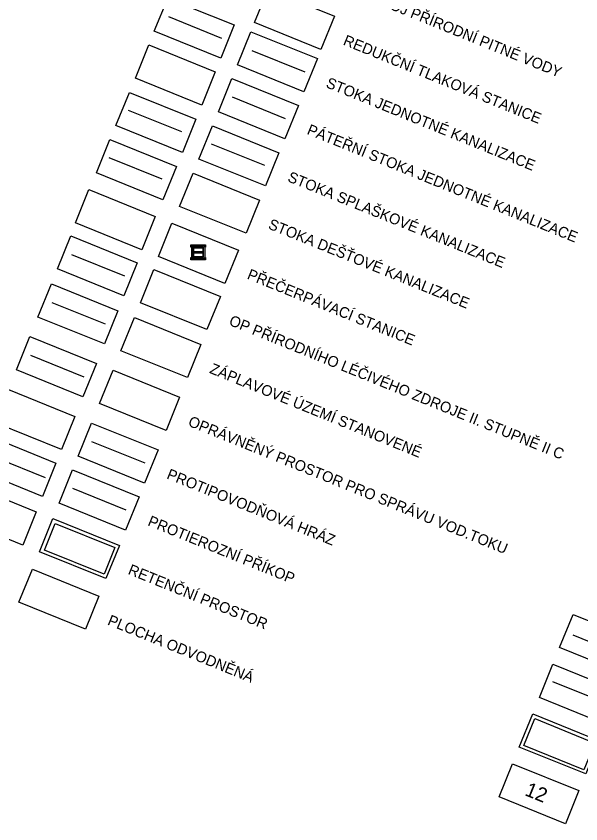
# Model space of a CAD drawing. Extents: x -522754 to -518969, y -1191121 to -1188171.
# Drawn here: x -520911 to -520123, y -1191020 to -1189893 of the extents above; entities that cross this region are included whole.
import ezdxf

# ---------------------------------------------------------------- set-up
doc = ezdxf.new("R2010")
doc.units = 0
for name, color, linetype in [('fpl_id', 7, 'Continuous'), ('hr_zast_uz_P_n', 7, 'Continuous'), ('HZU_P_s', 7, 'Continuous'), ('Implicitní', 7, 'Continuous'), ('kan_pater_j_n', 7, 'Continuous'), ('kan_stoka_j_n', 7, 'Continuous'), ('kan_stoka_j_s', 7, 'Continuous'), ('kan_stoka_s_n', 7, 'Continuous'), ('kan_stoka_s_s', 7, 'Continuous'), ('OPLZ_II_s', 7, 'Continuous'), ('pe_prikop_n', 7, 'Continuous'), ('pe_prikop_s', 7, 'Continuous'), ('pp_hraz_n', 7, 'Continuous'), ('ret_prostor_n', 7, 'Continuous'), ('sprava_toku_s', 7, 'Continuous'), ('zapl_uz_zdok_s', 7, 'Continuous'), ('zast_HD_s', 7, 'Continuous')]:
    doc.layers.add(name, color=color, linetype=linetype)

msp = doc.modelspace()

# ---------------------------------------------------------------- linework, layer by layer
at = {"layer": 'hr_zast_uz_P_n'}
msp.add_line((-520162.9, -1190821.2), (-520088.7, -1190851.2), dxfattribs=at)
at = {"layer": 'HZU_P_s'}
msp.add_line((-520134.5, -1190756.1), (-520060.4, -1190786.2), dxfattribs=at)
at = {"layer": 'Implicitní'}
for points in [[(-520559.8, -1189855.3), (-520467.1, -1189892.9), (-520485.9, -1189939.2), (-520578.5, -1189901.6)], [(-520699.6, -1189867.7), (-520606.9, -1189905.2), (-520625.7, -1189951.6), (-520718.4, -1189914)], [(-520583.7, -1189914.6), (-520491, -1189952.2), (-520509.8, -1189998.5), (-520602.5, -1189960.9)], [(-520726.1, -1189933), (-520633.4, -1189970.6), (-520652.2, -1190016.9), (-520744.8, -1189979.4)], [(-520610.2, -1189980), (-520517.5, -1190017.5), (-520536.3, -1190063.9), (-520629, -1190026.3)], [(-520753.2, -1189999.2), (-520660.5, -1190036.7), (-520679.3, -1190083), (-520772, -1190045.5)], [(-520637.3, -1190046), (-520544.6, -1190083.5), (-520563.4, -1190129.8), (-520656.1, -1190092.4)], [(-520780.3, -1190065.1), (-520687.6, -1190102.6), (-520706.4, -1190149), (-520799.1, -1190111.5)], [(-520664.4, -1190112), (-520571.7, -1190149.4), (-520590.5, -1190195.8), (-520683.2, -1190158.3)], [(-520809.6, -1190134.9), (-520717, -1190172.4), (-520735.7, -1190218.8), (-520828.4, -1190181.2)], [(-520693.8, -1190181.8), (-520601.1, -1190219.4), (-520619.9, -1190265.7), (-520712.6, -1190228.1)], [(-520834.9, -1190199.3), (-520742.2, -1190236.8), (-520761, -1190283.2), (-520853.7, -1190245.6)], [(-520719, -1190246.2), (-520626.3, -1190283.8), (-520645.1, -1190330.1), (-520737.8, -1190292.6)], [(-520862, -1190266.3), (-520769.4, -1190303.9), (-520788.1, -1190350.2), (-520880.8, -1190312.6)], [(-520746.2, -1190313.3), (-520653.5, -1190350.8), (-520672.3, -1190397.2), (-520765, -1190359.6)], [(-520891.9, -1190340), (-520799.2, -1190377.5), (-520818, -1190423.9), (-520910.7, -1190386.3)], [(-520776, -1190386.9), (-520683.4, -1190424.5), (-520702.1, -1190470.8), (-520794.8, -1190433.3)], [(-520921.7, -1190413.6), (-520829.1, -1190451.2), (-520847.8, -1190497.5), (-520940.5, -1190460)], [(-520805.9, -1190460.6), (-520713.2, -1190498.1), (-520732, -1190544.5), (-520824.7, -1190506.9)], [(-520948.2, -1190479), (-520855.6, -1190516.5), (-520874.3, -1190562.9), (-520967, -1190525.3)], [(-520832.4, -1190525.9), (-520739.7, -1190563.5), (-520758.5, -1190609.8), (-520851.2, -1190572.3)], [(-520975.7, -1190546.8), (-520883, -1190584.3), (-520901.8, -1190630.7), (-520994.5, -1190593.1)], [(-520859.9, -1190593.7), (-520767.2, -1190631.3), (-520786, -1190677.6), (-520878.6, -1190640.1)], [(-520888.5, -1190664.3), (-520795.8, -1190701.9), (-520814.6, -1190748.2), (-520907.2, -1190710.6)], [(-520134.3, -1190727.5), (-520041.6, -1190765), (-520060.4, -1190811.4), (-520153, -1190773.8)], [(-520162.4, -1190797), (-520069.7, -1190834.5), (-520088.5, -1190880.9), (-520181.2, -1190843.3)], [(-520190.5, -1190866.2), (-520097.8, -1190903.8), (-520116.6, -1190950.1), (-520209.3, -1190912.6)], [(-520187.6, -1190872.9), (-520103.8, -1190907), (-520119.1, -1190944.5), (-520202.9, -1190910.4)], [(-520218.7, -1190935.7), (-520126, -1190973.3), (-520144.8, -1191019.6), (-520237.4, -1190982.1)]]:
    msp.add_lwpolyline(points, close=True, dxfattribs=at)
at = {"layer": 'kan_pater_j_n'}
msp.add_line((-520610, -1190005.6), (-520535.9, -1190035.7), dxfattribs=at)
at = {"layer": 'kan_stoka_j_n'}
msp.add_line((-520582.5, -1189940.7), (-520508.3, -1189970.7), dxfattribs=at)
at = {"layer": 'kan_stoka_j_s'}
msp.add_line((-520698.8, -1189893.6), (-520624.6, -1189923.6), dxfattribs=at)
at = {"layer": 'kan_stoka_s_n'}
msp.add_line((-520639, -1190070.8), (-520564.8, -1190100.7), dxfattribs=at)
at = {"layer": 'kan_stoka_s_s'}
for p, q in [((-520754.9, -1190024), (-520680.7, -1190053.9)), ((-520781.9, -1190089.9), (-520707.8, -1190119.9))]:
    msp.add_line(p, q, dxfattribs=at)
at = {"layer": 'OPLZ_II_s'}
msp.add_line((-520834, -1190225.2), (-520759.9, -1190255.2), dxfattribs=at)
at = {"layer": 'pe_prikop_n'}
msp.add_line((-520832.5, -1190551.5), (-520758.3, -1190581.5), dxfattribs=at)
at = {"layer": 'pe_prikop_s'}
msp.add_line((-520944.8, -1190506.3), (-520870.7, -1190536.3), dxfattribs=at)
at = {"layer": 'pp_hraz_n'}
msp.add_line((-520806, -1190486.1), (-520731.8, -1190516.2), dxfattribs=at)
at = {"layer": 'ret_prostor_n'}
msp.add_lwpolyline([(-520856.5, -1190600.7), (-520773.5, -1190634.3), (-520788.5, -1190671.5), (-520871.6, -1190637.8)], close=True, dxfattribs=at)
at = {"layer": 'sprava_toku_s'}
msp.add_line((-520891.1, -1190365.9), (-520816.9, -1190395.9), dxfattribs=at)
at = {"layer": 'zapl_uz_zdok_s'}
msp.add_line((-520861.2, -1190292.2), (-520787.1, -1190322.3), dxfattribs=at)
at = {"layer": 'zast_HD_s'}
for points in [[(-520667.6, -1190215.3), (-520667.6, -1190212)], [(-520667.6, -1190212), (-520650.1, -1190212)], [(-520666.3, -1190213.3), (-520648.1, -1190213.3), (-520648.1, -1190231.5), (-520666.3, -1190231.5), (-520666.3, -1190213.3)], [(-520650.1, -1190213.3), (-520666.3, -1190213.3), (-520666.3, -1190215.3)], [(-520650.1, -1190212), (-520646.8, -1190212), (-520646.8, -1190215.3)], [(-520648.1, -1190215.3), (-520648.1, -1190213.3), (-520650.1, -1190213.3)], [(-520666.3, -1190215.3), (-520667.6, -1190215.3)], [(-520657.2, -1190215.1), (-520664.5, -1190215.1)], [(-520664.5, -1190215.1), (-520664.5, -1190229.7)], [(-520663.5, -1190221.9), (-520663.5, -1190216.1)], [(-520663.5, -1190216.1), (-520657.2, -1190216.1)], [(-520650.9, -1190221.9), (-520663.5, -1190221.9)], [(-520657.2, -1190228.7), (-520663.5, -1190228.7), (-520663.5, -1190222.9)], [(-520663.5, -1190222.9), (-520650.9, -1190222.9)], [(-520649.9, -1190215.1), (-520657.2, -1190215.1)], [(-520657.2, -1190215.1), (-520657.2, -1190216.1)], [(-520657.2, -1190216.1), (-520657.2, -1190215.1)], [(-520657.2, -1190216.1), (-520650.9, -1190216.1)], [(-520650.9, -1190222.9), (-520650.9, -1190228.7), (-520657.2, -1190228.7)], [(-520650.9, -1190216.1), (-520650.9, -1190221.9)], [(-520649.9, -1190229.7), (-520649.9, -1190215.1)], [(-520646.8, -1190215.3), (-520648.1, -1190215.3)], [(-520664.3, -1190232.8), (-520667.6, -1190232.8), (-520667.6, -1190229.5)], [(-520667.6, -1190229.5), (-520666.3, -1190229.5)], [(-520666.3, -1190229.5), (-520666.3, -1190231.5), (-520650.1, -1190231.5)], [(-520664.5, -1190229.7), (-520657.2, -1190229.7)], [(-520646.8, -1190229.5), (-520646.8, -1190232.8), (-520664.3, -1190232.8)], [(-520657.2, -1190229.7), (-520657.2, -1190228.7)], [(-520657.2, -1190228.7), (-520657.2, -1190229.7)], [(-520657.2, -1190229.7), (-520649.9, -1190229.7)], [(-520650.1, -1190231.5), (-520648.1, -1190231.5), (-520648.1, -1190229.5)], [(-520648.1, -1190229.5), (-520646.8, -1190229.5)]]:
    msp.add_lwpolyline(points, dxfattribs=at)

# ---------------------------------------------------------------- texts
at = {"layer": 'fpl_id'}
msp.add_text('12', height=20, rotation=337.938, dxfattribs=at).set_placement((-520202.8, -1190979.4))
at = {"layer": 'Implicitní'}
for s, rotation, p in [('ZDROJ PŘÍRODNÍ PITNÉ VODY', 337.9379, (-520429.6, -1189867)), ('REDUKČNÍ TLAKOVÁ STANICE', 337.9379, (-520456.1, -1189932.4)), ('STOKA JEDNOTNÉ KANALIZACE', 337.9379, (-520480.1, -1189991.7)), ('PÁTEŘNÍ STOKA JEDNOTNÉ KANALIZACE', 337.9379, (-520506.6, -1190057)), ('STOKA SPLAŠKOVÉ KANALIZACE', 337.9994, (-520533.6, -1190123)), ('STOKA DEŠŤOVÉ KANALIZACE', 337.9994, (-520560.7, -1190188.9)), ('PŘEČERPÁVACÍ STANICE', 337.9379, (-520590.1, -1190258.9)), ('OP PŘÍRODNÍHO LÉČIVÉHO ZDROJE II. STUPNĚ II C', 337.9379, (-520615.4, -1190323.3)), ('ZÁPLAVOVÉ ÚZEMÍ STANOVENÉ', 337.9379, (-520642.5, -1190390.3)), ('OPRÁVNĚNÝ PROSTOR PRO SPRÁVU VOD.TOKU', 337.9379, (-520672.4, -1190464)), ('PROTIPOVODŇOVÁ HRÁZ', 337.9379, (-520702.3, -1190537.6)), ('PROTIEROZNÍ PŘÍKOP', 337.9379, (-520728.7, -1190603)), ('RETENČNÍ PROSTOR', 337.9379, (-520756.2, -1190670.8)), ('PLOCHA ODVODNĚNÁ', 337.9381, (-520784.8, -1190741.4))]:
    msp.add_text(s, height=15, rotation=rotation, dxfattribs=at).set_placement(p)

doc.saveas('drawing.dxf')
